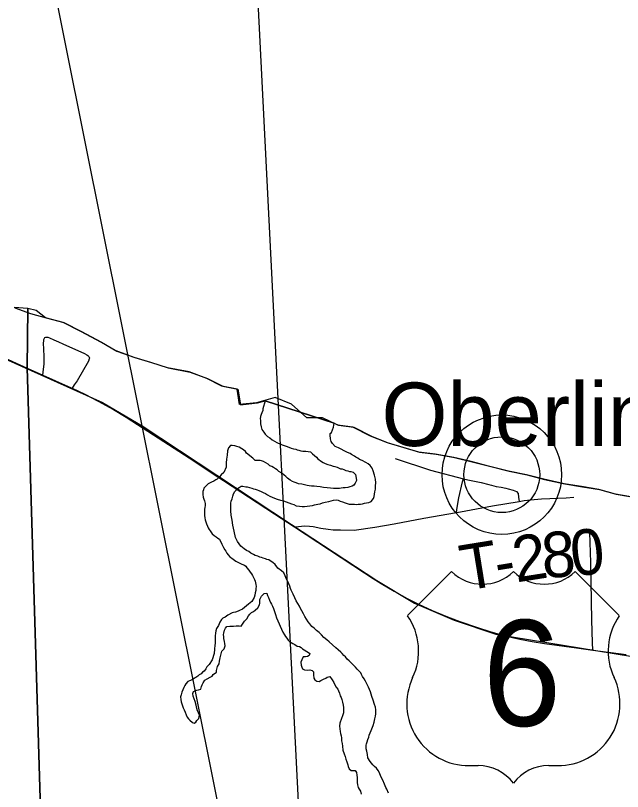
# Model space of a CAD drawing. Extents: x 0 to 34, y 0 to 22.
# Drawn here: x 5.679 to 6.435, y 18.183 to 19.15 of the extents above; entities that cross this region are included whole.
import ezdxf

# ---------------------------------------------------------------- set-up
doc = ezdxf.new("R2010")
doc.units = 0
for name, color, linetype in [('GM_X_Corporation', 7, 'Continuous'), ('GM_X_Major_Lake', 7, 'Continuous'), ('GM_X_Major_River', 7, 'Continuous'), ('GM_X_Rail_Line', 7, 'Continuous'), ('GM_X_Township_Road', 7, 'Continuous'), ('GM_X_Township_Road_Text', 7, 'Continuous'), ('GM_X_Unincorporated', 7, 'Continuous'), ('GM_X_Unincorporated_Location', 7, 'Continuous'), ('GM_X_Unincorporated_Text', 7, 'Continuous'), ('GM_X_US_Location', 7, 'Continuous'), ('GM_X_US_Route', 7, 'Continuous'), ('GM_X_US_Shield', 7, 'Continuous'), ('SH_Text', 7, 'Continuous')]:
    doc.layers.add(name, color=color, linetype=linetype)

msp = doc.modelspace()

# ---------------------------------------------------------------- linework, layer by layer
at = {"layer": 'GM_X_Corporation'}
for points in [[(5.62763, 16.84762), (5.7178, 16.84738), (5.77063, 16.84696), (5.77979, 16.84695), (5.77899, 16.85616), (5.77134, 16.946), (5.76703, 16.99245), (5.75371, 17.15047), (5.749, 17.20313), (5.74209, 17.28369), (5.73971, 17.31155), (5.73824, 17.32385), (5.73664, 17.33298), (5.73277, 17.35194), (5.73035, 17.50939), (5.7296, 17.53053), (5.72902, 17.54675), (5.72871, 17.5555), (5.69387, 18.71129), (5.69458, 18.78498), (5.67751, 18.78621)], [(6.45505, 18.54878), (6.42622, 18.55372), (6.40534, 18.5598), (6.38409, 18.56322), (6.36246, 18.56664), (6.33704, 18.57234), (6.31541, 18.57803), (6.29302, 18.58259), (6.26835, 18.58867), (6.24672, 18.59437), (6.2251, 18.59969), (6.20194, 18.60386), (6.18145, 18.60614), (6.14237, 18.61792), (6.1215, 18.62628), (6.09949, 18.63729), (6.08052, 18.63995), (6.06154, 18.64907), (6.04219, 18.64907), (6.02284, 18.66578), (6.00272, 18.67414), (5.97958, 18.66769), (5.95832, 18.6654), (5.95529, 18.68478), (5.93632, 18.68858), (5.91735, 18.69808), (5.89572, 18.70605), (5.86839, 18.71137), (5.8479, 18.71783), (5.82703, 18.72429), (5.80464, 18.73226), (5.78566, 18.74328), (5.76062, 18.75658), (5.73861, 18.7676), (5.7166, 18.77367), (5.70508, 18.78273), (5.69458, 18.78498), (5.67751, 18.78621)], [(6.45505, 18.54878), (6.42622, 18.55372), (6.40534, 18.5598), (6.38409, 18.56322), (6.36246, 18.56664), (6.33704, 18.57234), (6.31541, 18.57803), (6.29302, 18.58259), (6.26835, 18.58867), (6.24672, 18.59437), (6.2251, 18.59969), (6.20194, 18.60386), (6.18145, 18.60614), (6.14237, 18.61792), (6.1215, 18.62628), (6.09949, 18.63729), (6.08052, 18.63995), (6.06154, 18.64907), (6.04219, 18.64907), (6.02284, 18.66578), (6.00272, 18.67414), (5.97958, 18.66769), (5.95832, 18.6654), (5.95529, 18.68478), (5.93632, 18.68858), (5.91735, 18.69808), (5.89572, 18.70605), (5.86839, 18.71137), (5.8479, 18.71783), (5.82703, 18.72429), (5.80464, 18.73226), (5.78566, 18.74328), (5.76062, 18.75658), (5.73861, 18.7676), (5.7166, 18.77367), (5.70508, 18.78273), (5.69458, 18.78498), (5.69387, 18.71129), (5.72871, 17.5555)]]:
    msp.add_lwpolyline(points, dxfattribs=at)
at = {"layer": 'GM_X_Major_Lake'}
msp.add_line((5.99007, 18.67017), (6.07613, 18.64243), dxfattribs=at)
for points in [[(5.67848, 18.78612), (5.69821, 18.7789), (5.71756, 18.77358), (5.73957, 18.76751), (5.76158, 18.75649), (5.78663, 18.74319), (5.8056, 18.73218)], [(5.8056, 18.73218), (5.82799, 18.7242), (5.84886, 18.71774), (5.86935, 18.71128), (5.89667, 18.70596), (5.9183, 18.69799), (5.93728, 18.68849), (5.95625, 18.68469), (5.95928, 18.66532), (5.98054, 18.6676), (5.99007, 18.67017)], [(6.07613, 18.64243), (6.08148, 18.63987), (6.10045, 18.63721), (6.12246, 18.62619), (6.14333, 18.61783), (6.18242, 18.60606), (6.20291, 18.60378), (6.22606, 18.5996), (6.24768, 18.59428), (6.26931, 18.58858), (6.29398, 18.5825), (6.31637, 18.57795), (6.338, 18.57225), (6.36342, 18.56655), (6.38505, 18.56313), (6.4063, 18.55971), (6.42717, 18.55363), (6.45601, 18.54869)]]:
    msp.add_lwpolyline(points, dxfattribs=at)
at = {"layer": 'GM_X_Major_River'}
msp.add_line((6.07613, 18.64243), (5.99007, 18.67017), dxfattribs=at)
for points in [[(5.99007, 18.67017), (5.98745, 18.66031), (5.9871, 18.65802), (5.98598, 18.65535), (5.98524, 18.65306), (5.98451, 18.6504), (5.98378, 18.64773), (5.98417, 18.64583), (5.9842, 18.64355), (5.98422, 18.64127), (5.98501, 18.63785), (5.98618, 18.63444), (5.9885, 18.63104), (5.99004, 18.62878), (5.99311, 18.62577), (5.99579, 18.62389), (5.99885, 18.62164), (6.0019, 18.61977), (6.00458, 18.61827), (6.00649, 18.61753), (6.00878, 18.61641), (6.01145, 18.6153), (6.01373, 18.61456), (6.0164, 18.61344), (6.01983, 18.61233), (6.0225, 18.61122), (6.02555, 18.61049), (6.02822, 18.60975), (6.03012, 18.60901), (6.03203, 18.60865), (6.0347, 18.60791), (6.03698, 18.60755), (6.04078, 18.60721), (6.04382, 18.60686), (6.04649, 18.6065), (6.04917, 18.60387), (6.05415, 18.59973), (6.05569, 18.59784), (6.06028, 18.59447), (6.06219, 18.59334), (6.06486, 18.59223), (6.0683, 18.59074), (6.07134, 18.59001), (6.07477, 18.5889), (6.07706, 18.58816), (6.07973, 18.58743), (6.08163, 18.58669), (6.08392, 18.58557), (6.08583, 18.5852), (6.08811, 18.58446), (6.09078, 18.58335), (6.09307, 18.58299), (6.09497, 18.58225), (6.09688, 18.58189), (6.09954, 18.58115), (6.10261, 18.57814), (6.10342, 18.57359), (6.10382, 18.57093), (6.10233, 18.56749), (6.10046, 18.56519), (6.09857, 18.56366), (6.09554, 18.56287), (6.09289, 18.56208), (6.08985, 18.56167), (6.08719, 18.56165), (6.08492, 18.56125), (6.08264, 18.56084), (6.08074, 18.56083), (6.07884, 18.56081), (6.07504, 18.56077), (6.07162, 18.56112), (6.06744, 18.56184), (6.06287, 18.56218), (6.05869, 18.5629), (6.0545, 18.56324), (6.05108, 18.56359), (6.04766, 18.56394), (6.04499, 18.56429), (6.04233, 18.56465), (6.03928, 18.56538), (6.03586, 18.56611), (6.03167, 18.56683), (6.02862, 18.56794), (6.02633, 18.56868), (6.02405, 18.56942), (6.02137, 18.57129), (6.01793, 18.57392), (6.01601, 18.57581), (6.01371, 18.57768), (6.01103, 18.57994), (6.00721, 18.58218), (6.00491, 18.58406), (6.00299, 18.58556), (6.0007, 18.58706), (5.99841, 18.58818)], [(5.94727, 18.53296), (5.94722, 18.53828), (5.94756, 18.54247), (5.94791, 18.54513), (5.94903, 18.54818), (5.94975, 18.55123), (5.95086, 18.55428), (5.95236, 18.55696), (5.95424, 18.55888), (5.95574, 18.56079), (5.95763, 18.56233), (5.96027, 18.56388), (5.96255, 18.5639), (5.96598, 18.56317), (5.96788, 18.56281), (5.97055, 18.56207), (5.97359, 18.56134), (5.9755, 18.5606), (5.97779, 18.55986), (5.98007, 18.55912), (5.98236, 18.55838), (5.98503, 18.55727), (5.98771, 18.55577), (5.99038, 18.55466), (5.99305, 18.55316), (5.99611, 18.55129), (5.99878, 18.55017), (6.00183, 18.54868), (6.00526, 18.54757), (6.00907, 18.54647), (6.01288, 18.54536), (6.01631, 18.54426), (6.01974, 18.54315), (6.0228, 18.54166), (6.02584, 18.54092), (6.0289, 18.53943), (6.03308, 18.53871), (6.03613, 18.53836), (6.03917, 18.53839), (6.04903, 18.53962), (6.05168, 18.54041), (6.05358, 18.5408), (6.05586, 18.54121), (6.05851, 18.54199), (6.06154, 18.54316), (6.06495, 18.54395), (6.0695, 18.54476), (6.07253, 18.54555), (6.07518, 18.54633), (6.07898, 18.54674), (6.08088, 18.54638), (6.08355, 18.54527), (6.0866, 18.54416), (6.08965, 18.54304), (6.09232, 18.54231), (6.09461, 18.54157), (6.09879, 18.54123), (6.10145, 18.54125), (6.10373, 18.5409), (6.10601, 18.5413), (6.10867, 18.54132), (6.11132, 18.54173), (6.11398, 18.54251), (6.11625, 18.54291), (6.11929, 18.54332), (6.12231, 18.54487), (6.12494, 18.54832), (6.12567, 18.55099), (6.1264, 18.55403), (6.12676, 18.5567), (6.12748, 18.56013), (6.12744, 18.56431), (6.12779, 18.56811), (6.12736, 18.57267), (6.12617, 18.5776), (6.1246, 18.58291), (6.12343, 18.58632), (6.12074, 18.58971), (6.11844, 18.59159), (6.11539, 18.59309), (6.1108, 18.5957), (6.10775, 18.59719), (6.10545, 18.59869), (6.10316, 18.59981), (6.10125, 18.60131), (6.09781, 18.60318), (6.0959, 18.60431), (6.09285, 18.6058), (6.08865, 18.60766), (6.08483, 18.6099), (6.08139, 18.61139), (6.0772, 18.61325), (6.07412, 18.61703), (6.0722, 18.61929), (6.07141, 18.6227), (6.07098, 18.62726), (6.07096, 18.62954), (6.07285, 18.6307), (6.07506, 18.63718), (6.07613, 18.64243)], [(5.99841, 18.58818), (5.99612, 18.5893), (5.99382, 18.59118), (5.99114, 18.59306), (5.98809, 18.59455), (5.9858, 18.59529), (5.9839, 18.59565), (5.97972, 18.59561), (5.97782, 18.59559), (5.97475, 18.5986), (5.96709, 18.60499), (5.96555, 18.60688), (5.96325, 18.60914), (5.96096, 18.61026), (5.9579, 18.61251), (5.95485, 18.61324), (5.95257, 18.61398), (5.94914, 18.61433), (5.94686, 18.61431), (5.94461, 18.61163), (5.94313, 18.60781), (5.9428, 18.60248), (5.94209, 18.59754), (5.94175, 18.59297), (5.94178, 18.58955), (5.94181, 18.58727), (5.93883, 18.58078), (5.93544, 18.57809), (5.93318, 18.57541), (5.93055, 18.57272), (5.92866, 18.57156), (5.9264, 18.57002), (5.92337, 18.56885), (5.91921, 18.56691), (5.91657, 18.56422), (5.91394, 18.56116), (5.9132, 18.55925), (5.91246, 18.55734), (5.9125, 18.55354), (5.91291, 18.55013), (5.9137, 18.54747), (5.91485, 18.54558), (5.91565, 18.54217), (5.91529, 18.53988), (5.91493, 18.53722), (5.91457, 18.53532), (5.9146, 18.53266), (5.91462, 18.53037), (5.91465, 18.52733), (5.91506, 18.5243), (5.91546, 18.52202), (5.91625, 18.51937), (5.91703, 18.51671), (5.9182, 18.51406), (5.91936, 18.51179), (5.92052, 18.5099), (5.92167, 18.50801), (5.92437, 18.50462), (5.92667, 18.50236), (5.92935, 18.50048), (5.93126, 18.49898), (5.93317, 18.49786), (5.93628, 18.49142), (5.93821, 18.48726), (5.93976, 18.48461), (5.9413, 18.48273), (5.94246, 18.48046), (5.944, 18.47819), (5.9463, 18.47593), (5.9486, 18.47405), (5.95358, 18.4703), (5.95625, 18.46918), (5.95854, 18.46806), (5.96121, 18.46657), (5.96426, 18.46546), (5.96617, 18.46434), (5.96733, 18.46206), (5.96964, 18.45905), (5.97156, 18.45678), (5.97311, 18.45452), (5.97427, 18.45263), (5.97581, 18.44998), (5.97697, 18.44733), (5.97775, 18.44544), (5.97855, 18.44126), (5.97896, 18.43899), (5.9786, 18.43632), (5.97863, 18.43366), (5.97789, 18.43099), (5.97716, 18.42795), (5.97643, 18.42528), (5.97344, 18.41993), (5.96929, 18.41685), (5.96703, 18.41455), (5.96439, 18.41262), (5.96175, 18.41069), (5.95835, 18.40876), (5.95646, 18.40798), (5.95305, 18.40681), (5.95078, 18.40641), (5.94888, 18.40601)], [(6.11579, 18.23652), (6.11577, 18.2388), (6.11575, 18.24108), (6.11649, 18.24299), (6.11723, 18.24528), (6.11796, 18.24832), (6.11907, 18.251), (6.11981, 18.25366), (6.12092, 18.25634), (6.12203, 18.25939), (6.12315, 18.26168), (6.12463, 18.26549), (6.12573, 18.26969), (6.12683, 18.27388), (6.12756, 18.27731), (6.12791, 18.27997), (6.12789, 18.28263), (6.12786, 18.28529), (6.12745, 18.28833), (6.12628, 18.29174), (6.12471, 18.29705), (6.12314, 18.30197), (6.12119, 18.30766), (6.12002, 18.31069), (6.11885, 18.31334), (6.11768, 18.31598), (6.11652, 18.31826), (6.11498, 18.3209), (6.11343, 18.32393), (6.1115, 18.32657), (6.10996, 18.32922), (6.10918, 18.33111), (6.10649, 18.33413), (6.10457, 18.33601), (6.10265, 18.33827), (6.10073, 18.34053), (6.09882, 18.34204), (6.0969, 18.34392), (6.0946, 18.34618), (6.0923, 18.34844), (6.08999, 18.35108), (6.08807, 18.35296), (6.08615, 18.35522), (6.08423, 18.35711), (6.08117, 18.35974), (6.0781, 18.36237), (6.06967, 18.36989), (6.06699, 18.37253), (6.06316, 18.37515), (6.06009, 18.37855), (6.0574, 18.38156), (6.05396, 18.38381), (6.05127, 18.38683), (6.04821, 18.38908), (6.0459, 18.3921), (6.0436, 18.39474), (6.04166, 18.39814), (6.03935, 18.40154), (6.0378, 18.40495), (6.03586, 18.40835), (6.03431, 18.41138), (6.03277, 18.4144), (6.03083, 18.41781), (6.0289, 18.42083), (6.02697, 18.42461), (6.02502, 18.42916), (6.02386, 18.43181), (6.0227, 18.43408), (6.02153, 18.43634), (6.02075, 18.43938), (6.01958, 18.44203), (6.01841, 18.44506), (6.01686, 18.44809), (6.01492, 18.45225), (6.01337, 18.45566), (6.01068, 18.45829), (6.00609, 18.46167), (6.00263, 18.4662), (5.99956, 18.46883), (5.99651, 18.4707), (5.9946, 18.47182), (5.99231, 18.47256), (5.9904, 18.47331), (5.98774, 18.47404), (5.98545, 18.47478), (5.98354, 18.47552), (5.98087, 18.47664), (5.97782, 18.47737), (5.97553, 18.47887), (5.97248, 18.48036), (5.9698, 18.48223), (5.96712, 18.48373), (5.96407, 18.4856), (5.95985, 18.48898), (5.95562, 18.49503), (5.95329, 18.49995), (5.95169, 18.50791), (5.9501, 18.51512), (5.9489, 18.52157), (5.9477, 18.52764), (5.94727, 18.53296)], [(5.96943, 18.4024), (5.97093, 18.40432), (5.97319, 18.40624), (5.97546, 18.40778), (5.97772, 18.40932), (5.98111, 18.4124), (5.98298, 18.41584), (5.98334, 18.41812), (5.98367, 18.42269), (5.98553, 18.42688), (5.98892, 18.42996), (5.99234, 18.43037), (5.99312, 18.42771), (5.99429, 18.42506), (5.99546, 18.42165), (5.99701, 18.41901), (5.99817, 18.41674), (5.99933, 18.41447), (6.0005, 18.41144), (6.00167, 18.40765), (6.00285, 18.40386), (6.00441, 18.39969), (6.01218, 18.3819), (6.01412, 18.3785), (6.01565, 18.37661), (6.0172, 18.37434), (6.01874, 18.37208), (6.02066, 18.37019), (6.02256, 18.36907), (6.02448, 18.36795), (6.02715, 18.36645), (6.03021, 18.36458), (6.03288, 18.36385), (6.03478, 18.36272), (6.0367, 18.36122), (6.03861, 18.3601), (6.04205, 18.35785), (6.04396, 18.35673), (6.04588, 18.35523), (6.04514, 18.35294), (6.04287, 18.35177), (6.04021, 18.35137), (6.03756, 18.35134), (6.03569, 18.34753), (6.03458, 18.34448), (6.035, 18.34068), (6.03578, 18.33841), (6.03656, 18.33613), (6.03923, 18.33502), (6.04342, 18.33468), (6.04569, 18.33508), (6.04874, 18.33434), (6.05028, 18.33246), (6.05031, 18.32866), (6.05073, 18.32448), (6.05189, 18.32259), (6.05457, 18.32071), (6.05723, 18.32036), (6.0595, 18.32152), (6.0629, 18.32345), (6.06555, 18.32462), (6.06744, 18.32578), (6.07047, 18.32657), (6.07355, 18.32241), (6.07548, 18.31939), (6.07703, 18.31637), (6.07858, 18.31334), (6.0805, 18.3107), (6.08128, 18.3088), (6.08283, 18.30577), (6.08362, 18.30274), (6.08478, 18.30047), (6.08556, 18.2982), (6.08635, 18.29478), (6.08715, 18.29099), (6.08756, 18.28795), (6.08759, 18.28453), (6.08762, 18.28149), (6.08652, 18.27768), (6.08503, 18.27424), (6.08319, 18.26852), (6.08285, 18.26472), (6.08326, 18.2613), (6.08367, 18.25827), (6.08407, 18.25561), (6.08486, 18.25295), (6.08527, 18.2503), (6.0853, 18.2465), (6.0861, 18.24308), (6.0865, 18.24005), (6.08693, 18.23511), (6.0885, 18.23018), (6.08967, 18.22715), (6.09046, 18.22374), (6.09164, 18.22033), (6.09319, 18.21654), (6.09359, 18.21464), (6.09476, 18.21161), (6.09706, 18.20973), (6.09934, 18.20938), (6.10238, 18.2094)], [(5.94888, 18.40601), (5.94359, 18.40292), (5.94057, 18.40061), (5.93754, 18.39944), (5.93566, 18.39752), (5.93379, 18.39447), (5.93193, 18.39027), (5.92969, 18.38644), (5.92858, 18.38339), (5.92823, 18.38073), (5.92788, 18.3773), (5.92793, 18.37236), (5.92797, 18.3678), (5.92761, 18.3659), (5.92728, 18.36057), (5.92657, 18.35524), (5.92437, 18.34724), (5.92063, 18.3415), (5.91761, 18.33881), (5.9165, 18.33614), (5.91425, 18.33346), (5.91236, 18.33192), (5.91048, 18.33), (5.90821, 18.32884), (5.90633, 18.3273), (5.90406, 18.32538), (5.90217, 18.3246), (5.89915, 18.32267), (5.89613, 18.32112), (5.89386, 18.32034), (5.89122, 18.31766), (5.8901, 18.31537), (5.88899, 18.31307), (5.88639, 18.30697), (5.88566, 18.30392), (5.88492, 18.30125), (5.88533, 18.29784), (5.88574, 18.29518), (5.88692, 18.29139), (5.88809, 18.2876), (5.88926, 18.28495), (5.89042, 18.2823), (5.89198, 18.27889), (5.89314, 18.27586), (5.89468, 18.27397), (5.89622, 18.27209), (5.89967, 18.26946), (5.90158, 18.26834), (5.90384, 18.26988), (5.90496, 18.27179), (5.9076, 18.27448), (5.90832, 18.27866), (5.90715, 18.28131), (5.90599, 18.28396), (5.9052, 18.287), (5.9044, 18.29079), (5.90321, 18.29534), (5.90049, 18.30216), (5.90008, 18.30558), (5.90081, 18.30786), (5.90498, 18.3098), (5.90725, 18.3102), (5.9099, 18.31099), (5.91101, 18.31442), (5.91175, 18.31633), (5.91286, 18.319), (5.91512, 18.32206), (5.91776, 18.32361), (5.92154, 18.32593), (5.92419, 18.32709), (5.92531, 18.329), (5.92946, 18.33208), (5.92944, 18.33398), (5.93091, 18.33894), (5.93278, 18.34238), (5.9335, 18.34581), (5.93422, 18.34999), (5.93495, 18.35342), (5.93642, 18.35838), (5.93906, 18.36106), (5.94054, 18.36488), (5.94013, 18.36791), (5.93935, 18.37019), (5.93855, 18.37398), (5.93853, 18.37626), (5.9385, 18.37892), (5.93886, 18.38083), (5.93959, 18.38426), (5.94071, 18.38693), (5.94259, 18.38885), (5.94638, 18.38926), (5.94904, 18.38929), (5.95094, 18.38931), (5.95398, 18.38971), (5.95588, 18.38973), (5.95778, 18.38975), (5.96044, 18.38939), (5.96268, 18.39322), (5.96456, 18.39552), (5.96719, 18.39858), (5.96943, 18.4024)], [(6.14368, 18.18128), (6.14174, 18.18621), (6.1402, 18.18847), (6.13864, 18.19264), (6.13669, 18.19756), (6.13436, 18.2021), (6.13242, 18.20664), (6.13087, 18.20967), (6.12857, 18.21231), (6.12626, 18.21457), (6.12434, 18.21683), (6.12242, 18.21871), (6.12089, 18.2206), (6.11818, 18.22552), (6.11738, 18.22969), (6.11658, 18.23349), (6.11579, 18.23652)], [(6.10238, 18.2094), (6.10392, 18.20714), (6.10433, 18.20372), (6.10474, 18.20106), (6.10476, 18.19916), (6.10478, 18.19688), (6.1048, 18.1946), (6.10521, 18.19156), (6.106, 18.18853), (6.10716, 18.18626), (6.1087, 18.18399), (6.10988, 18.1802)]]:
    msp.add_lwpolyline(points, dxfattribs=at)
at = {"layer": 'GM_X_Rail_Line'}
msp.add_lwpolyline([(4.15567, 19.03949), (4.37138, 19.02191), (4.47313, 19.01067), (4.54928, 18.99506), (4.89823, 18.92512), (4.98063, 18.91388), (5.294, 18.88266), (5.32646, 18.87516), (5.65418, 18.7278), (5.78776, 18.66785), (5.83708, 18.63913), (6.0231, 18.51611), (6.12922, 18.44618), (6.17604, 18.41808), (6.22535, 18.39685), (6.27716, 18.37936), (6.48815, 18.34502), (6.68791, 18.31816), (6.87885, 18.29227)], dxfattribs=at)
at = {"layer": 'GM_X_Township_Road'}
for points in [[(5.71329, 18.70215), (5.71416, 18.70963), (5.71489, 18.7158), (5.71511, 18.71892), (5.71503, 18.72515), (5.71456, 18.73454), (5.71429, 18.74197), (5.71452, 18.745), (5.71474, 18.74646), (5.71504, 18.74754), (5.71537, 18.74821), (5.71608, 18.74903)], [(5.71608, 18.74903), (5.71731, 18.74944), (5.71813, 18.74952), (5.71881, 18.74952), (5.7198, 18.74929), (5.72156, 18.7486), (5.72699, 18.74618), (5.73275, 18.74355), (5.7382, 18.74092), (5.76543, 18.7289), (5.76812, 18.72743), (5.76953, 18.72642), (5.77051, 18.72544), (5.77109, 18.72437), (5.77128, 18.7233), (5.7712, 18.7224), (5.77007, 18.7195), (5.75597, 18.6952), (5.75251, 18.69001), (5.74972, 18.68582)], [(6.15217, 18.59808), (6.19609, 18.58387), (6.23696, 18.57311)], [(6.22823, 18.53101), (6.22928, 18.53725), (6.23126, 18.54908), (6.23572, 18.56935), (6.23696, 18.57311)], [(6.23696, 18.57311), (6.24248, 18.57166), (6.25902, 18.56819), (6.26855, 18.56572), (6.27172, 18.56523), (6.27791, 18.56357), (6.28393, 18.56257), (6.28973, 18.56139), (6.29255, 18.56051), (6.2987, 18.55896), (6.30285, 18.55715), (6.30492, 18.55456), (6.3057, 18.55016), (6.30628, 18.54476)], [(6.22823, 18.53101), (6.23339, 18.53193), (6.27313, 18.53922), (6.30628, 18.54476)], [(6.30628, 18.54476), (6.31271, 18.54584), (6.32498, 18.54735), (6.33403, 18.54815), (6.36503, 18.54945), (6.37428, 18.55026)], [(6.02661, 18.51306), (6.03175, 18.51362), (6.03924, 18.51445), (6.04534, 18.5139), (6.04973, 18.51365), (6.05947, 18.51163), (6.06862, 18.51018), (6.07475, 18.50957), (6.08393, 18.50922), (6.10089, 18.50908), (6.12683, 18.51261), (6.15076, 18.51692), (6.18749, 18.52382), (6.22823, 18.53101)], [(6.39797, 18.35949), (6.3977, 18.369), (6.3969, 18.397), (6.39538, 18.46865), (6.39445, 18.50597)]]:
    msp.add_lwpolyline(points, dxfattribs=at)
at = {"layer": 'GM_X_Unincorporated'}
for radius in [0.0744, 0.04716]:
    msp.add_circle((6.28474, 18.57807), radius, dxfattribs=at)
at = {"layer": 'GM_X_Unincorporated_Location'}
msp.add_line((6.28474, 18.57807), (6.28474, 18.57807), dxfattribs=at)
at = {"layer": 'GM_X_US_Route'}
for points in [[(5.35635, 18.86232), (5.37478, 18.85442), (5.38604, 18.84935), (5.43217, 18.82858), (5.45686, 18.81746), (5.4897, 18.80278), (5.50792, 18.79464), (5.54757, 18.7767), (5.5919, 18.75647), (5.61542, 18.74572), (5.64605, 18.73216), (5.6609, 18.72559), (5.69409, 18.71074)], [(5.69409, 18.71074), (5.71329, 18.70215), (5.74879, 18.68625), (5.74972, 18.68582), (5.76563, 18.67833), (5.7822, 18.66985), (5.80119, 18.6593), (5.81714, 18.6497), (5.85108, 18.62781), (5.89548, 18.59919), (5.9265, 18.5785), (5.93824, 18.57084)], [(5.93824, 18.57084), (6.00199, 18.52926), (6.02661, 18.51306), (6.11362, 18.45581), (6.12115, 18.45096)], [(6.12115, 18.45096), (6.13454, 18.44234), (6.15059, 18.43279), (6.16699, 18.42384), (6.18092, 18.41687), (6.19789, 18.40908), (6.21512, 18.40186), (6.23255, 18.39516), (6.25314, 18.38802), (6.27097, 18.38246), (6.28899, 18.37752), (6.30719, 18.37333), (6.32247, 18.37035), (6.33784, 18.3679), (6.37785, 18.3622), (6.39797, 18.35949), (6.43945, 18.3539)]]:
    msp.add_lwpolyline(points, dxfattribs=at)
at = {"layer": 'GM_X_US_Shield'}
for p, q in [((6.22226, 18.4574), (6.16733, 18.40247)), ((6.431, 18.40247), (6.37607, 18.4574)), ((6.24424, 18.2157), (6.25522, 18.2157)), ((6.34311, 18.2157), (6.3541, 18.2157))]:
    msp.add_line(p, q, dxfattribs=at)
for centre, radius, start, end in [((6.26072, 18.49663), 0.05493, 225.573, 314.427), ((6.33762, 18.49663), 0.05493, 225.573, 314.427), ((6.10434, 18.35835), 0.0769, 334.54712, 35.00093), ((6.494, 18.35835), 0.0769, 144.99907, 205.45288), ((6.24338, 18.2926), 0.0769, 154.83192, 270.63826), ((6.35496, 18.2926), 0.0769, 269.36174, 25.16808), ((6.25522, 18.16077), 0.05493, 36.8699, 90), ((6.34311, 18.16077), 0.05493, 90, 143.1301)]:
    msp.add_arc(centre, radius, start, end, dxfattribs=at)
at = {"layer": 'SH_Text'}
msp.add_lwpolyline([(5.95502, 19.68612), (6.06483, 17.50305), (5.62674, 19.68612)], close=True, dxfattribs=at)

# ---------------------------------------------------------------- texts
at = {"layer": 'GM_X_Township_Road_Text'}
for s, rotation, p in [('2', 8.97722, (6.30274, 18.44376)), ('8', 3.80161, (6.33597, 18.44907)), ('0', 5.52879, (6.37275, 18.45154)), ('T', 9.20657, (6.23782, 18.43324)), ('-', 9.1877, (6.27976, 18.44004))]:
    msp.add_text(s, height=0.05682, rotation=rotation, dxfattribs=at).set_placement(p)
at = {"layer": 'GM_X_Unincorporated_Text'}
msp.add_text('Oberlin Beach', height=0.0789773, rotation=0.00001, dxfattribs=at).set_placement((6.135, 18.61382))
at = {"layer": 'GM_X_US_Location'}
for s, p in [('/', (6.29911, 18.33002)), ('0', (6.2991, 18.33002))]:
    msp.add_text(s, height=0.000189, dxfattribs=at).set_placement(p)
msp.add_text('6', height=0.000189, rotation=0.00001, dxfattribs=at).set_placement((6.28, 18.29081))
at = {"layer": 'GM_X_US_Shield'}
msp.add_text('6', height=0.13184, dxfattribs=at).set_placement((6.26085, 18.26514))

doc.saveas('drawing.dxf')
